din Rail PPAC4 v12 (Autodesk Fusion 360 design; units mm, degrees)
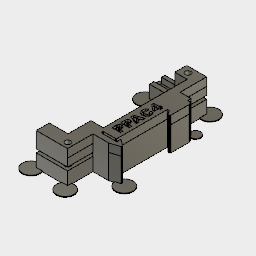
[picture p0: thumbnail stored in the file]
sketch "din_clip"
  line L1 (24.4607, 210.1295) -> (24.2926, 210.382)
  line L2 (-1.27, 219.4915) -> (-1.27, 209.4914)
  line L3 (19.7556, 279.4) -> (-1.27, 279.4)
  line L4 (-1.27, 210.2556) -> (-1.27, 190.3236)
  line L5 (18.3484, 212.746) -> (18.5627, 213.0637)
  line L6 (19.8915, 213.383) -> (19.8915, 211.4531)
  line L7 (-1.27, 258.0569) -> (19.7556, 258.0569)
  line L8 (22.4891, 257.9684) -> (22.0557, 258.6171)
  line L9 (9.0022, 211.6091) -> (8.8787, 211.953)
  line L10 (22.6413, 244.7031) -> (22.6413, 257.2029)
  line L11 (-1.27, 251.7434) -> (4.7097, 251.7434)
  line L12 (20.2976, 213.578) -> (20.0331, 213.6083)
  line L13 (24.2695, 209.5838) -> (24.4521, 209.826)
  line L14 (23.9801, 209.4914) -> (24.2695, 209.5838)
  line L15 (22.6413, 257.2029) -> (22.4891, 257.9684)
  line L16 (22.4949, 244.3496) -> (22.6413, 244.7031)
  line L17 (21.5847, 244.2032) -> (22.1415, 244.2032)
  line L18 (18.5627, 213.0637) -> (18.6412, 213.4529)
  line L19 (22.1415, 244.2032) -> (22.4949, 244.3496)
  line L20 (9.3591, 211.4531) -> (9.0022, 211.6091)
  line L21 (-1.27, 209.4914) -> (23.9801, 209.4914)
  line L22 (19.7556, 258.0569) -> (19.7556, 279.4)
  line L23 (21.0514, 244.3572) -> (21.5847, 244.2032)
  line L24 (-1.27, 279.4) -> (-1.27, 258.0569)
  line L25 (4.7097, 251.7434) -> (4.7099, 219.4915)
  line L26 (18.6412, 213.4529) -> (18.6412, 246.9531)
  line L27 (4.7099, 219.4915) -> (-1.27, 219.4915)
  line L28 (9.3591, 212.4532) -> (17.6415, 212.4532)
  line L29 (24.2926, 210.382) -> (20.2976, 213.578)
  line L30 (20.6821, 244.7723) -> (21.0514, 244.3572)
  line L31 (20.0331, 213.6083) -> (19.8915, 213.383)
  line L32 (22.0557, 258.6171) -> (21.4066, 259.0509)
  line L33 (7.2672, 190.3236) -> (7.2672, 210.2556)
  line L34 (18.0304, 212.5317) -> (18.3484, 212.746)
  line L35 (8.9953, 212.2968) -> (9.3591, 212.4532)
  line L36 (-1.27, 259.2036) -> (-1.27, 251.7434)
  line L37 (5.4884, 259.2031) -> (-1.27, 259.2036)
  line L38 (-1.27, 190.3236) -> (7.2672, 190.3236)
  line L39 (21.4066, 259.0509) -> (20.6415, 259.2031)
  line L40 (19.6414, 246.9531) -> (20.6821, 244.7723)
  line L41 (19.8915, 211.4531) -> (9.3591, 211.4531)
  line L42 (17.6415, 212.4532) -> (18.0304, 212.5317)
  line L43 (7.2672, 210.2556) -> (-1.27, 210.2556)
  line L44 (8.8787, 211.953) -> (8.9953, 212.2968)
  line L45 (20.6415, 259.2031) -> (5.4884, 259.2031)
  line L46 (18.6412, 246.9531) -> (19.6414, 246.9531)
  line L47 (24.4521, 209.826) -> (24.4607, 210.1295)
extrude "Extrude3" sketch "din_clip" blind 12.7
box_primitive "BoxPrimitive1" DistanceX 15.24 DistanceY 7.62 DistanceZ 3.81 OffsetDistanceX 0 OffsetDistanceY 0
step "MoveBody2"
step "MoveBody3"
step "MoveBody4"
offset_faces "OffsetFaces1" distance 6.096
combine "Combine3"
box_primitive "BoxPrimitive2" DistanceX 15.24 DistanceY 12.7 DistanceZ 7.62 OffsetDistanceX -7.62 OffsetDistanceY 12.7
step "MoveBody5"
offset_faces "OffsetFaces2" distance 15.24
combine "Combine6"
box_primitive "BoxPrimitive3" DistanceX 28.448 DistanceY 0.8719 DistanceZ 15.24 OffsetDistanceX 0 OffsetDistanceY 0
step "MoveBody13"
step "MoveBody14"
combine "Combine9"
box_primitive "BoxPrimitive5" DistanceX 2.54 DistanceY 20.32 DistanceZ 17.78 OffsetDistanceX 2.54 OffsetDistanceY -10.16
step "MoveBody22"
step "MoveBody23"
step "MoveBody24"
step "MoveBody25"
step "MoveBody26"
combine "Combine14"
offset_faces "OffsetFaces16" distance 1.27
box_primitive "BoxPrimitive6" DistanceX 2.54 DistanceY 5.08 DistanceZ 12.7 OffsetDistanceX -5.08 OffsetDistanceY 0
offset_faces "OffsetFaces31" distance 7.62
box_primitive "BoxPrimitive14" DistanceX 1.778 DistanceY 10.16 DistanceZ 99.06 OffsetDistanceX 0 OffsetDistanceY 0
step "MoveBody34"
step "MoveBody35"
combine "Combine15"
cylinder_primitive "CylinderPrimitive2" Height 17.78 Diameter 3.81
step "MoveBody36"
step "MoveBody37"
offset_faces "OffsetFaces99" distance 4
offset_faces "OffsetFaces100" distance 5
step "MoveBody38"
step "MoveBody39"
combine "Combine16"
step "MoveBody40"
combine "Combine17"
offset_faces "OffsetFaces36" distance -2.54
offset_faces "OffsetFaces37" distance -2.54
offset_faces "OffsetFaces38" distance -2.54
offset_faces "OffsetFaces39" distance -2.54
offset_faces "OffsetFaces40" distance -2.286
offset_faces "OffsetFaces41" distance -2.286
offset_faces "OffsetFaces42" distance 2.54
box_primitive "BoxPrimitive16" DistanceX 8.001 DistanceY 6.35 DistanceZ 12.7 OffsetDistanceX 0 OffsetDistanceY 0
box_primitive "BoxPrimitive26" DistanceX 5.461 DistanceY 6.35 DistanceZ 12.7 OffsetDistanceX 0 OffsetDistanceY 0
box_primitive "BoxPrimitive27" DistanceX 25.4 DistanceY 7.3819 DistanceZ -6.35 OffsetDistanceX 0 OffsetDistanceY 0
box_primitive "BoxPrimitive28" DistanceX 1.778 DistanceY 17.78 DistanceZ -5.08 OffsetDistanceX 0 OffsetDistanceY 0
offset_faces "OffsetFaces43" distance -2.54
offset_faces "OffsetFaces44" distance -2.54
offset_faces "OffsetFaces45" distance -1.27
offset_faces "OffsetFaces46" distance -1.27
box_primitive "BoxPrimitive23" DistanceX 5.461 DistanceY 2.54 DistanceZ 7.62 OffsetDistanceX 0 OffsetDistanceY 0
combine "Combine22"
box_primitive "BoxPrimitive24" DistanceX 7.5 DistanceY 8.784 DistanceZ 38.1 OffsetDistanceX 0 OffsetDistanceY 0
box_primitive "BoxPrimitive25" DistanceX 0.254 DistanceY 60 DistanceZ 101.6 OffsetDistanceX 2.4765 OffsetDistanceY 0
step "MoveBody68"
combine "Combine30"
step "MoveBody69"
offset_faces "OffsetFaces49" distance 2.54
sketch "Sketch48"
  curve K1 (4.9025, -4.0874) -> (4.9025, -32.6773)
  curve K2 (-3.0975, -4.0874) -> (4.9025, -4.0874)
  curve K3 (-3.0975, -32.6773) -> (-3.0975, -4.0874)
  curve K4 (4.9025, -32.6773) -> (-3.0975, -32.6773)
extrude "Extrude4" new body sketch "Sketch48" blind 0.635
offset_faces "OffsetFaces50" distance 2.54
offset_faces "OffsetFaces60" distance -0.5
offset_faces "OffsetFaces54" distance -1.27
step "MoveBody100"
offset_faces "OffsetFaces55" distance 1
step "MoveBody101"
offset_faces "OffsetFaces56" distance 1
offset_faces "OffsetFaces57" distance 1
offset_faces "OffsetFaces58" distance 1
offset_faces "OffsetFaces59" distance 1
step "MoveBody103"
step "MoveBody104"
step "MoveBody105"
step "MoveBody106"
step "MoveBody107"
step "MoveBody108"
step "MoveBody109"
step "MoveBody122"
step "MoveBody123"
step "MoveBody124"
step "MoveBody125"
step "MoveBody126"
step "MoveBody129"
step "MoveBody130"
step "MoveBody131"
step "MoveBody132"
step "MoveBody133"
combine "Combine45"
step "MoveBody110"
offset_faces "OffsetFaces61" distance -2.54
combine "Combine42"
box_primitive "BoxPrimitive29" DistanceX 7.501 DistanceY 7.9769 DistanceZ 2 OffsetDistanceX 0 OffsetDistanceY 0
box_primitive "BoxPrimitive30" DistanceX 7.501 DistanceY 7.9769 DistanceZ 12.7 OffsetDistanceX 0 OffsetDistanceY 0
box_primitive "BoxPrimitive31" DistanceX 5.08 DistanceY 13.5382 DistanceZ -3.81 OffsetDistanceX -1.016 OffsetDistanceY 0
offset_faces "OffsetFaces62" distance 2.54
offset_faces "OffsetFaces63" distance 2.54
offset_faces "OffsetFaces64" distance 2.54
box_primitive "BoxPrimitive32" DistanceX 10.041 DistanceY 56.7593 DistanceZ -9.906 OffsetDistanceX 0 OffsetDistanceY 0
offset_faces "OffsetFaces65" distance -1.27
offset_faces "OffsetFaces66" distance 1.27
offset_faces "OffsetFaces67" distance 1.27
offset_faces "OffsetFaces68" distance 1.27
offset_faces "OffsetFaces69" distance 1.27
offset_faces "OffsetFaces70" distance 1.27
offset_faces "OffsetFaces71" distance 2.54
offset_faces "OffsetFaces72" distance -1.15
offset_faces "OffsetFaces73" distance -1.15
offset_faces "OffsetFaces113" distance -1
cylinder_primitive "CylinderPrimitive3" Height 0.5 Diameter 12
step "MoveBody111"
step "MoveBody128"
copy_paste_bodies "CopyPasteBodies6"
step "MoveBody112"
copy_paste_bodies "CopyPasteBodies7"
step "MoveBody113"
copy_paste_bodies "CopyPasteBodies8"
step "MoveBody114"
copy_paste_bodies "CopyPasteBodies9"
step "MoveBody115"
copy_paste_bodies "CopyPasteBodies10"
step "MoveBody116"
copy_paste_bodies "CopyPasteBodies11"
step "MoveBody117"
step "MoveBody137"
step "MoveBody138"
step "MoveBody139"
step "MoveBody140"
step "MoveBody141"
step "MoveBody142"
step "MoveBody119"
offset_faces "OffsetFaces114" distance 1
box_primitive "BoxPrimitive36" DistanceX 14.351 DistanceY 1.2626 DistanceZ 1 OffsetDistanceX 0 OffsetDistanceY 0
box_primitive "BoxPrimitive37" DistanceX 14.351 DistanceY 1.2626 DistanceZ 1 OffsetDistanceX 0 OffsetDistanceY 0
box_primitive "BoxPrimitive38" DistanceX 9.041 DistanceY 1.2526 DistanceZ 1 OffsetDistanceX 0 OffsetDistanceY 0
offset_faces "OffsetFaces74" distance 1
offset_faces "OffsetFaces75" distance 1
offset_faces "OffsetFaces76" distance 1
offset_faces "OffsetFaces77" distance 1
offset_faces "OffsetFaces78" distance -0.5
offset_faces "OffsetFaces79" distance -0.5
offset_faces "OffsetFaces80" distance 1
offset_faces "OffsetFaces81" distance -0.5
offset_faces "OffsetFaces82" distance -0.5
offset_faces "OffsetFaces83" distance -0.5
offset_faces "OffsetFaces84" distance 1.5
offset_faces "OffsetFaces86" distance -1.5
offset_faces "OffsetFaces87" distance -0.06
offset_faces "OffsetFaces88" distance -0.05
offset_faces "OffsetFaces89" distance 3.5
offset_faces "OffsetFaces90" distance 3.5
offset_faces "OffsetFaces91" distance 3.5
offset_faces "OffsetFaces92" distance 3.5
offset_faces "OffsetFaces93" distance 3.5
copy_paste_bodies "CopyPasteBodies15"
step "MoveBody134"
combine "Combine46"
cylinder_primitive "CylinderPrimitive4" Height 0.5 Diameter 6.939
step "MoveBody136"
offset_faces "OffsetFaces94" distance -1
offset_faces "OffsetFaces95" distance -1
offset_faces "OffsetFaces96" distance -1
offset_faces "OffsetFaces97" distance -1
offset_faces "OffsetFaces98" distance -1
offset_faces "OffsetFaces101" distance -2
offset_faces "OffsetFaces102" distance -2
offset_faces "OffsetFaces103" distance -2
offset_faces "OffsetFaces104" distance -2
offset_faces "OffsetFaces105" distance -2
offset_faces "OffsetFaces106" distance 1.5
box_primitive "BoxPrimitive33" DistanceX 23.59 DistanceY 47.3434 DistanceZ 1.5 OffsetDistanceX 0 OffsetDistanceY 0
box_primitive "BoxPrimitive34" DistanceX 11.351 DistanceY 9.7131 DistanceZ 1.5 OffsetDistanceX 0 OffsetDistanceY 0
box_primitive "BoxPrimitive35" DistanceX 9.541 DistanceY 7.2631 DistanceZ 1.5 OffsetDistanceX 0 OffsetDistanceY 0
combine "Combine47"
offset_faces "OffsetFaces107" distance -0.5
offset_faces "OffsetFaces108" distance -1
offset_faces "OffsetFaces109" distance -1
offset_faces "OffsetFaces110" distance -1
offset_faces "OffsetFaces111" distance -1
offset_faces "OffsetFaces112" distance -1
step "MoveBody127"
combine "Combine48"
step "MoveBody143"
step "MoveBody144"
offset_faces "OffsetFaces115" distance -0.92
offset_faces "OffsetFaces116" distance -1
offset_faces "OffsetFaces117" distance 0.08
combine "Combine49"
offset_faces "OffsetFaces119" distance 0.5
offset_faces "OffsetFaces120" distance 0.5
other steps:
base_feature "Base Feature6"
base_feature "Base Feature7"
base_feature "Base Feature8"
base_feature "Base Feature9"
base_feature "Base Feature10"
base_feature "Base Feature11"
base_feature "Base Feature15"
